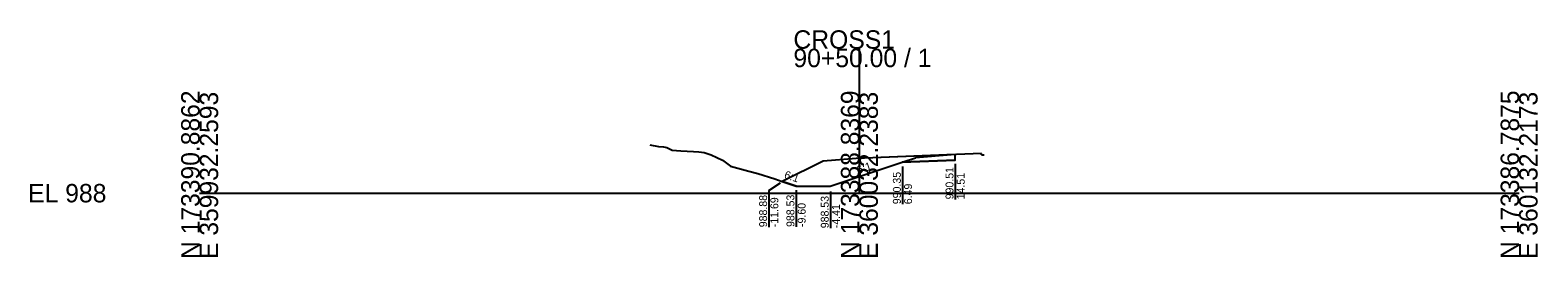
# Model space of a CAD drawing. Extents: x -26 to 1403, y -10 to 11027.
# Drawn here: x -25.7 to 202.8, y 5490.3 to 5524.8 of the extents above; entities that cross this region are included whole.
import ezdxf

# ---------------------------------------------------------------- set-up
doc = ezdxf.new("R2010")
doc.units = 0
for name, color, linetype in [('Default', 7, 'Continuous'), ('P_E_XS_Ground', 7, 'Continuous'), ('P_XS', 7, 'Continuous'), ('P_XS_EAR_CommonGrnd', 7, 'Continuous'), ('P_XS_Lane', 7, 'Continuous'), ('P_XS_Rock', 7, 'Continuous')]:
    doc.layers.add(name, color=color, linetype=linetype)

msp = doc.modelspace()

# ---------------------------------------------------------------- linework, layer by layer
at = {"layer": 'Default'}
for p, q in [((100, 5500), (100, 5521.95)), ((0, 5500), (100, 5500)), ((100, 5500), (200, 5500))]:
    msp.add_line(p, q, dxfattribs=at)
at = {"layer": 'P_E_XS_Ground'}
for p, q in [((68.25, 5507.32), (69.56, 5507.09)), ((69.56, 5507.09), (70.31, 5507.04)), ((70.31, 5507.04), (70.79, 5506.93)), ((70.79, 5506.93), (71.62, 5506.53)), ((71.62, 5506.53), (72.93, 5506.43)), ((72.93, 5506.43), (74.84, 5506.35)), ((74.84, 5506.35), (75.66, 5506.3)), ((75.66, 5506.3), (76.49, 5506.18)), ((76.49, 5506.18), (77.51, 5505.8)), ((77.51, 5505.8), (79.23, 5505.02)), ((118.51, 5506.01), (99.5, 5505.25)), ((118.51, 5505.81), (118.51, 5506.01)), ((118.51, 5505.81), (118.89, 5505.82)), ((79.23, 5505.02), (80.47, 5504.11)), ((80.47, 5504.11), (83.25, 5503.36)), ((83.25, 5503.36), (84.59, 5503.01)), ((94.5, 5504.85), (88.31, 5501.76)), ((99.5, 5505.25), (94.5, 5504.85)), ((84.59, 5503.01), (87.16, 5502.16)), ((87.16, 5502.16), (88.31, 5501.76))]:
    msp.add_line(p, q, dxfattribs=at)
at = {"layer": 'P_XS'}
for p in [(106.49, 5504.7), (114.51, 5505.85)]:
    msp.add_line(p, (108.51, 5505.37), dxfattribs=at)
at = {"layer": 'P_XS_EAR_CommonGrnd'}
msp.add_lwpolyline([(94.5, 5504.85), (88.31, 5501.76), (90.4, 5501.06), (95.59, 5501.06), (106.49, 5504.7), (114.51, 5505.02), (114.51, 5505.85), (99.5, 5505.25)], close=True, dxfattribs=at)
at = {"layer": 'P_XS_Lane'}
for p, q in [((114.51, 5505.02), (114.51, 5505.85)), ((95.59, 5501.06), (106.49, 5504.7)), ((114.51, 5505.02), (106.49, 5504.7)), ((90.4, 5501.06), (88.31, 5501.76)), ((90.4, 5501.06), (95.59, 5501.06))]:
    msp.add_line(p, q, dxfattribs=at)
at = {"layer": 'P_XS_Rock'}
for p, q in [((106.53, 5504.03), (106.53, 5498.32)), ((114.51, 5504.46), (114.51, 5499.05)), ((86.26, 5500.42), (88.06, 5501.59)), ((86.26, 5500.42), (86.26, 5494.82)), ((90.4, 5500.45), (90.4, 5494.86)), ((95.6, 5500.26), (95.6, 5494.67))]:
    msp.add_line(p, q, dxfattribs=at)

# ---------------------------------------------------------------- texts
at = {"layer": 'Default'}
for s, p in [('CROSS1', (90, 5521.95)), ('90+50.00 / 1', (90, 5519.15)), ('EL 988', (-26, 5498.6))]:
    msp.add_text(s, height=2.8, dxfattribs=at).set_placement(p)
for s, p in [('N 173390.8862', (0, 5490)), ('E 359932.2593', (2.8, 5490)), ('N 173388.8369', (100, 5490)), ('E 360032.2383', (102.8, 5490)), ('N 173386.7875', (200, 5490)), ('E 360132.2173', (202.8, 5490))]:
    msp.add_text(s, height=2.8, rotation=90, dxfattribs=at).set_placement(p)
at = {"layer": 'P_XS_Rock'}
for s, rotation, p in [('6:1', 341.5651, (88.51, 5502.31)), ('6:1', 18.4349, (99.83, 5502.92)), ('990.35', 90, (106.28, 5498.32)), ('990.51', 90, (114.26, 5499.06)), ('6.49', 90, (107.98, 5498.32)), ('14.51', 90, (115.96, 5499.06)), ('988.88', 90, (86.01, 5494.82)), ('-11.69', 90, (87.71, 5494.82)), ('988.53', 90, (90.15, 5494.86)), ('988.53', 90, (95.35, 5494.67)), ('-9.60', 90, (91.85, 5494.86)), ('-4.41', 90, (97.05, 5494.67))]:
    msp.add_text(s, height=1.2, rotation=rotation, dxfattribs=at).set_placement(p)

doc.saveas('drawing.dxf')
